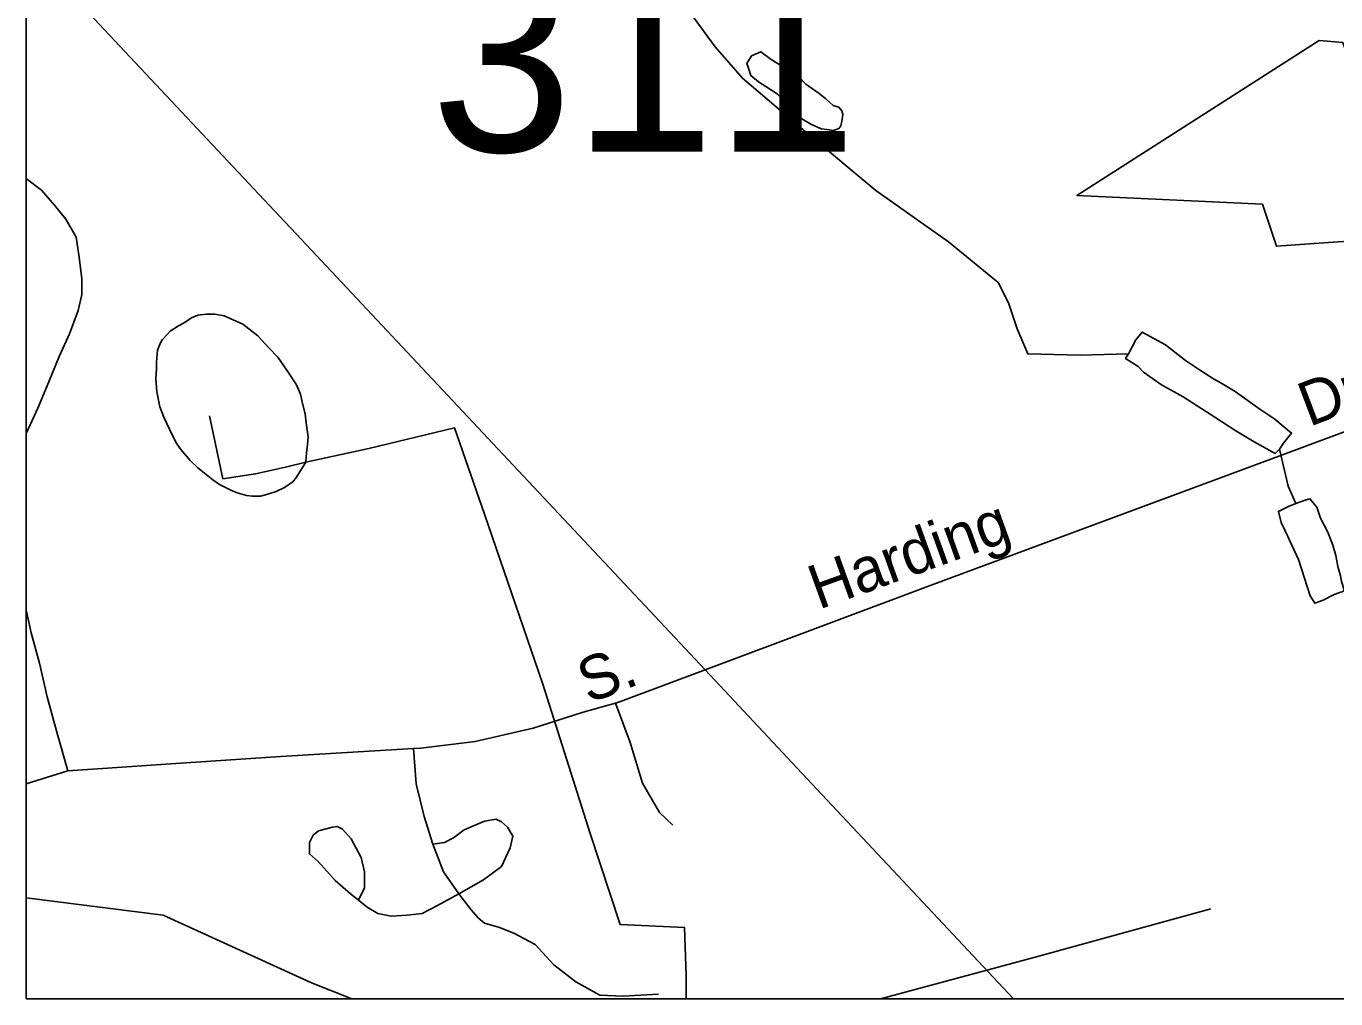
# Model space of a CAD drawing. Extents: x 2315291 to 2336543, y 597177 to 615230.
# Drawn here: x 2315744 to 2318553, y 597530 to 599617 of the extents above; entities that cross this region are included whole.
import ezdxf

# ---------------------------------------------------------------- set-up
doc = ezdxf.new("R2010")
doc.units = 0
for name, color, linetype in [('Exist Boundary Political City Limit New', 7, 'Continuous'), ('Exist Hydrographic Misc Water Feature', 7, 'Continuous'), ('Exist Road Non-System Type 51', 7, 'Continuous'), ('Exist Road Non-System Type 51 Label', 7, 'Continuous'), ('Exist Road Secondary Structure Standard Bridge Number Label', 7, 'Continuous'), ('Exist Utilities Electrical Transmission Line', 7, 'Continuous'), ('Map Preparation Boundary City Limit Buffer Line', 7, 'Continuous')]:
    doc.layers.add(name, color=color, linetype=linetype)

msp = doc.modelspace()

# ---------------------------------------------------------------- linework, layer by layer
at = {"layer": 'Exist Boundary Political City Limit New'}
for points in [[(2315744.5, 604723.7), (2315744.5, 597529.5), (2327185.3, 597529.5)], [(2318568.5, 599581.4), (2318700.5, 599210), (2318661, 599213.2), (2318679.8, 599162), (2318547.8, 599152.8), (2318426, 599144.2), (2318396.2, 599234.6), (2317998.2, 599253.6), (2318517.8, 599585.9), (2318568.5, 599581.4)]]:
    msp.add_lwpolyline(points, dxfattribs=at)
at = {"layer": 'Exist Hydrographic Misc Water Feature'}
for points in [[(2318108.7, 598913.8), (2318004.9, 598910.8), (2317893.2, 598913.4), (2317870.2, 598967.5), (2317851.7, 599023), (2317829.4, 599066.9), (2317722.8, 599153.6), (2317567.1, 599263.8), (2317420.1, 599386.5), (2317280.9, 599504.8), (2317222.4, 599572), (2317161.5, 599655.3)], [(2317431, 599482.2), (2317445.5, 599472.3), (2317459.3, 599460.5), (2317475.3, 599446.7), (2317487.4, 599442.9), (2317493.7, 599435), (2317495.8, 599427), (2317493.9, 599413.1), (2317492.1, 599402.8), (2317487.8, 599397), (2317476.1, 599393.1), (2317461.9, 599394.8), (2317449.8, 599396.6), (2317427.7, 599406.4), (2317408, 599417.9), (2317379.3, 599447.8), (2317355.3, 599471.7), (2317331.1, 599487.1), (2317314.9, 599497.2), (2317298.9, 599511), (2317293, 599528.9), (2317290.5, 599536.6), (2317300.4, 599552.9), (2317310.4, 599557.1), (2317320.5, 599561.3), (2317342.4, 599545.4), (2317386.9, 599518), (2317408.8, 599500.1), (2317416.8, 599492), (2317431, 599482.2)], [(2316344.4, 598681), (2316346, 598701), (2316347.7, 598719), (2316349.5, 598735.3), (2316345.2, 598765.2), (2316343, 598785), (2316336.8, 598807), (2316332.5, 598826.7), (2316324.3, 598847), (2316306.5, 598874.4), (2316284.1, 598906.2), (2316265.7, 598926), (2316241.5, 598951.9), (2316209.3, 598977.5), (2316168.9, 598994.9), (2316149, 598998.7), (2316130.7, 598998.6), (2316112.9, 598996.4), (2316098.8, 598990.5), (2316083, 598980.3), (2316071.5, 598973.9), (2316053.2, 598962), (2316047.5, 598955.6), (2316035.8, 598943.6), (2316031.9, 598935.7), (2316025.8, 598921.6), (2316024.3, 598895.4), (2316024.1, 598881.6), (2316022.7, 598859.6), (2316024.7, 598831.7), (2316031.3, 598799.9), (2316039.7, 598777.9), (2316057.5, 598739.9), (2316067.8, 598720.1), (2316076, 598708.4), (2316096.3, 598684.6), (2316112.5, 598668.8), (2316144.7, 598642.9), (2316159.2, 598633), (2316183.2, 598621.3), (2316197, 598615.5), (2316216.9, 598609.7), (2316229, 598607.9), (2316246.8, 598608), (2316262.8, 598612.1), (2316280.8, 598618.3), (2316298.7, 598626.6), (2316316.5, 598638.9), (2316324.5, 598649), (2316344.4, 598681)], [(2318108.7, 598913.8), (2318124.3, 598943.9), (2318138, 598960.1), (2318188.2, 598932.6), (2318231.1, 598899), (2318263.3, 598877.6), (2318291.4, 598859.9), (2318305.3, 598852.1), (2318337.3, 598832.4), (2318390.2, 598794.8), (2318422.4, 598773.3), (2318458.5, 598743.5), (2318440.9, 598721.5), (2318432.9, 598709.3)], [(2318432.9, 598709.3), (2318423.2, 598699.4), (2318378.5, 598724.8), (2318338.7, 598748.6), (2318296.1, 598776.1), (2318225.8, 598821.1), (2318179.6, 598846.8), (2318141.3, 598874.4), (2318129.2, 598886), (2318102.7, 598903.8), (2318108.7, 598913.8)], [(2316137.3, 598780.6), (2316166.6, 598645.3), (2316236.6, 598655.9), (2316300.5, 598670.5), (2316344.4, 598681)], [(2316344.4, 598681), (2316479.7, 598710.5), (2316663.5, 598754.6), (2316727.4, 598569.4), (2316852.9, 598205), (2316954.2, 597883.9), (2317018.2, 597689), (2317156.6, 597682.4), (2317159.7, 597578.5), (2317160.2, 597529.5)], [(2318467.7, 598592.1), (2318451.5, 598629.8), (2318432.9, 598709.3)], [(2318467.7, 598592.1), (2318477.8, 598595.9), (2318489.9, 598600.1), (2318497.9, 598602.2), (2318512.4, 598584.2), (2318520.4, 598560.7), (2318536.6, 598530.6), (2318546.9, 598502.7), (2318553.4, 598480.7), (2318557.5, 598457), (2318563.5, 598437), (2318565.7, 598424.9), (2318572.3, 598405.2), (2318550.2, 598396.8), (2318526.4, 598384.6), (2318508.3, 598378.4), (2318498.3, 598394.5), (2318485.8, 598434.1), (2318473.3, 598472), (2318445, 598533.5), (2318436.3, 598551.8), (2318430.2, 598575.5), (2318452.3, 598585.9), (2318467.7, 598592.1)], [(2316443.1, 597529.5), (2316356.3, 597564.1), (2316038.3, 597708.7), (2315744.5, 597745.9)], [(2318285.2, 597722.5), (2317908.8, 597618.6), (2317576.9, 597529.5)]]:
    msp.add_lwpolyline(points, dxfattribs=at)
at = {"layer": 'Exist Road Non-System Type 51'}
for points in [[(2315744.5, 598742.7), (2315769.1, 598797.2), (2315793.2, 598853.6), (2315815.4, 598908), (2315837.5, 598956.3), (2315855.6, 599006.7), (2315863.7, 599041), (2315863.7, 599075.2), (2315857.7, 599125.6), (2315851.6, 599163.9), (2315829.5, 599202.2), (2315805.3, 599232.4), (2315777.1, 599264.6), (2315744.9, 599288.8), (2315744.5, 599289)], [(2315744.5, 598362.1), (2315744.9, 598360.9), (2315755, 598314.6), (2315773.1, 598250.1), (2315789.2, 598177.5), (2315811.3, 598096.9), (2315833.5, 598018.4)], [(2317131.2, 597902.3), (2317102.7, 597929), (2317066.5, 597991.9), (2317039.8, 598079.5), (2317008.3, 598164.2)], [(2316575.1, 598066.8), (2316580.8, 597990.9), (2316597.9, 597920.4), (2316617, 597861.3)], [(2316457, 597741.3), (2316470.3, 597767.9), (2316470.3, 597802.2), (2316462.7, 597832.7), (2316441.7, 597872.8), (2316422.7, 597893.7), (2316411.3, 597899.4), (2316401.7, 597897.5), (2316371.3, 597889.9), (2316359.8, 597880.4), (2316352.2, 597865.1), (2316352.2, 597840.4), (2316371.3, 597823.2), (2316407.5, 597783.2), (2316439.8, 597754.6), (2316457, 597741.3)], [(2316672.2, 597754.6), (2316725.5, 597785.1), (2316763.6, 597813.7), (2316782.7, 597853.7), (2316788.4, 597878.5), (2316777, 597897.5), (2316763.6, 597909), (2316752.2, 597914.7), (2316727.4, 597910.9), (2316683.6, 597891.8), (2316660.8, 597874.7), (2316641.7, 597865.1), (2316617, 597861.3)], [(2316617, 597861.3), (2316639.8, 597802.2), (2316672.2, 597754.6)], [(2316672.2, 597754.6), (2316626.5, 597729.8), (2316594.1, 597712.7), (2316561.7, 597708.9), (2316527.5, 597706.9), (2316498.9, 597712.7), (2316476, 597726), (2316457, 597741.3)], [(2316672.2, 597754.6), (2316698.9, 597720.3), (2316714.1, 597703.1), (2316727.4, 597691.7), (2316759.8, 597682.2), (2316790.3, 597670.7), (2316836, 597646), (2316876, 597602.1), (2316923.6, 597565.9), (2316975.1, 597537.3), (2317024.6, 597535.4), (2317100.8, 597539.2)]]:
    msp.add_lwpolyline(points, dxfattribs=at)
at = {"layer": 'Exist Road Non-System Type 51 Label'}
msp.add_lwpolyline([(2319875.9, 599227.8), (2318529.3, 598730.4), (2318439.4, 598697), (2318076.9, 598562.3), (2317685.5, 598416.9), (2317200.8, 598235.4), (2317018.9, 598167.2), (2317008.3, 598164.2), (2316938.9, 598144.3), (2316832.2, 598110), (2316707.5, 598081.8), (2316590.7, 598067.7), (2316575.1, 598066.8), (2316290.6, 598049.6), (2316055, 598033.5), (2315908, 598023.4), (2315833.5, 598018.4), (2315744.5, 597990.8)], dxfattribs=at)
at = {"layer": 'Exist Utilities Electrical Transmission Line'}
for p, q in [((2315744.5, 599788.2), (2316288, 599208.6)), ((2316288, 599208.6), (2316323.2, 599171.1)), ((2316323.2, 599171.1), (2317200.8, 598235.4))]:
    msp.add_line(p, q, dxfattribs=at)
msp.add_lwpolyline([(2317200.8, 598235.4), (2317419.2, 598002.6), (2317861.9, 597529.5)], dxfattribs=at)
at = {"layer": 'Map Preparation Boundary City Limit Buffer Line'}
for points in [[(2315744.5, 604723.7), (2315744.5, 597529.5), (2327185.3, 597529.5)], [(2318568.5, 599581.4), (2318700.5, 599210), (2318661, 599213.2), (2318679.8, 599162), (2318547.8, 599152.8), (2318426, 599144.2), (2318396.2, 599234.6), (2317998.2, 599253.6), (2318517.8, 599585.9), (2318568.5, 599581.4)]]:
    msp.add_lwpolyline(points, dxfattribs=at)

# ---------------------------------------------------------------- texts
at = {"layer": 'Exist Road Non-System Type 51 Label'}
for s, rotation, p in [('Dr.', 20.7896, (2318496.2, 598756.3)), ('Harding', 19.8434, (2317444.2, 598364.1)), ('S.', 21.2452, (2316950.8, 598162.3))]:
    msp.add_text(s, height=95, rotation=rotation, dxfattribs=at).set_placement(p)
at = {"layer": 'Exist Road Secondary Structure Standard Bridge Number Label'}
msp.add_text('311', height=410.1, dxfattribs=at).set_placement((2316611.7, 599347.4))

doc.saveas('drawing.dxf')
